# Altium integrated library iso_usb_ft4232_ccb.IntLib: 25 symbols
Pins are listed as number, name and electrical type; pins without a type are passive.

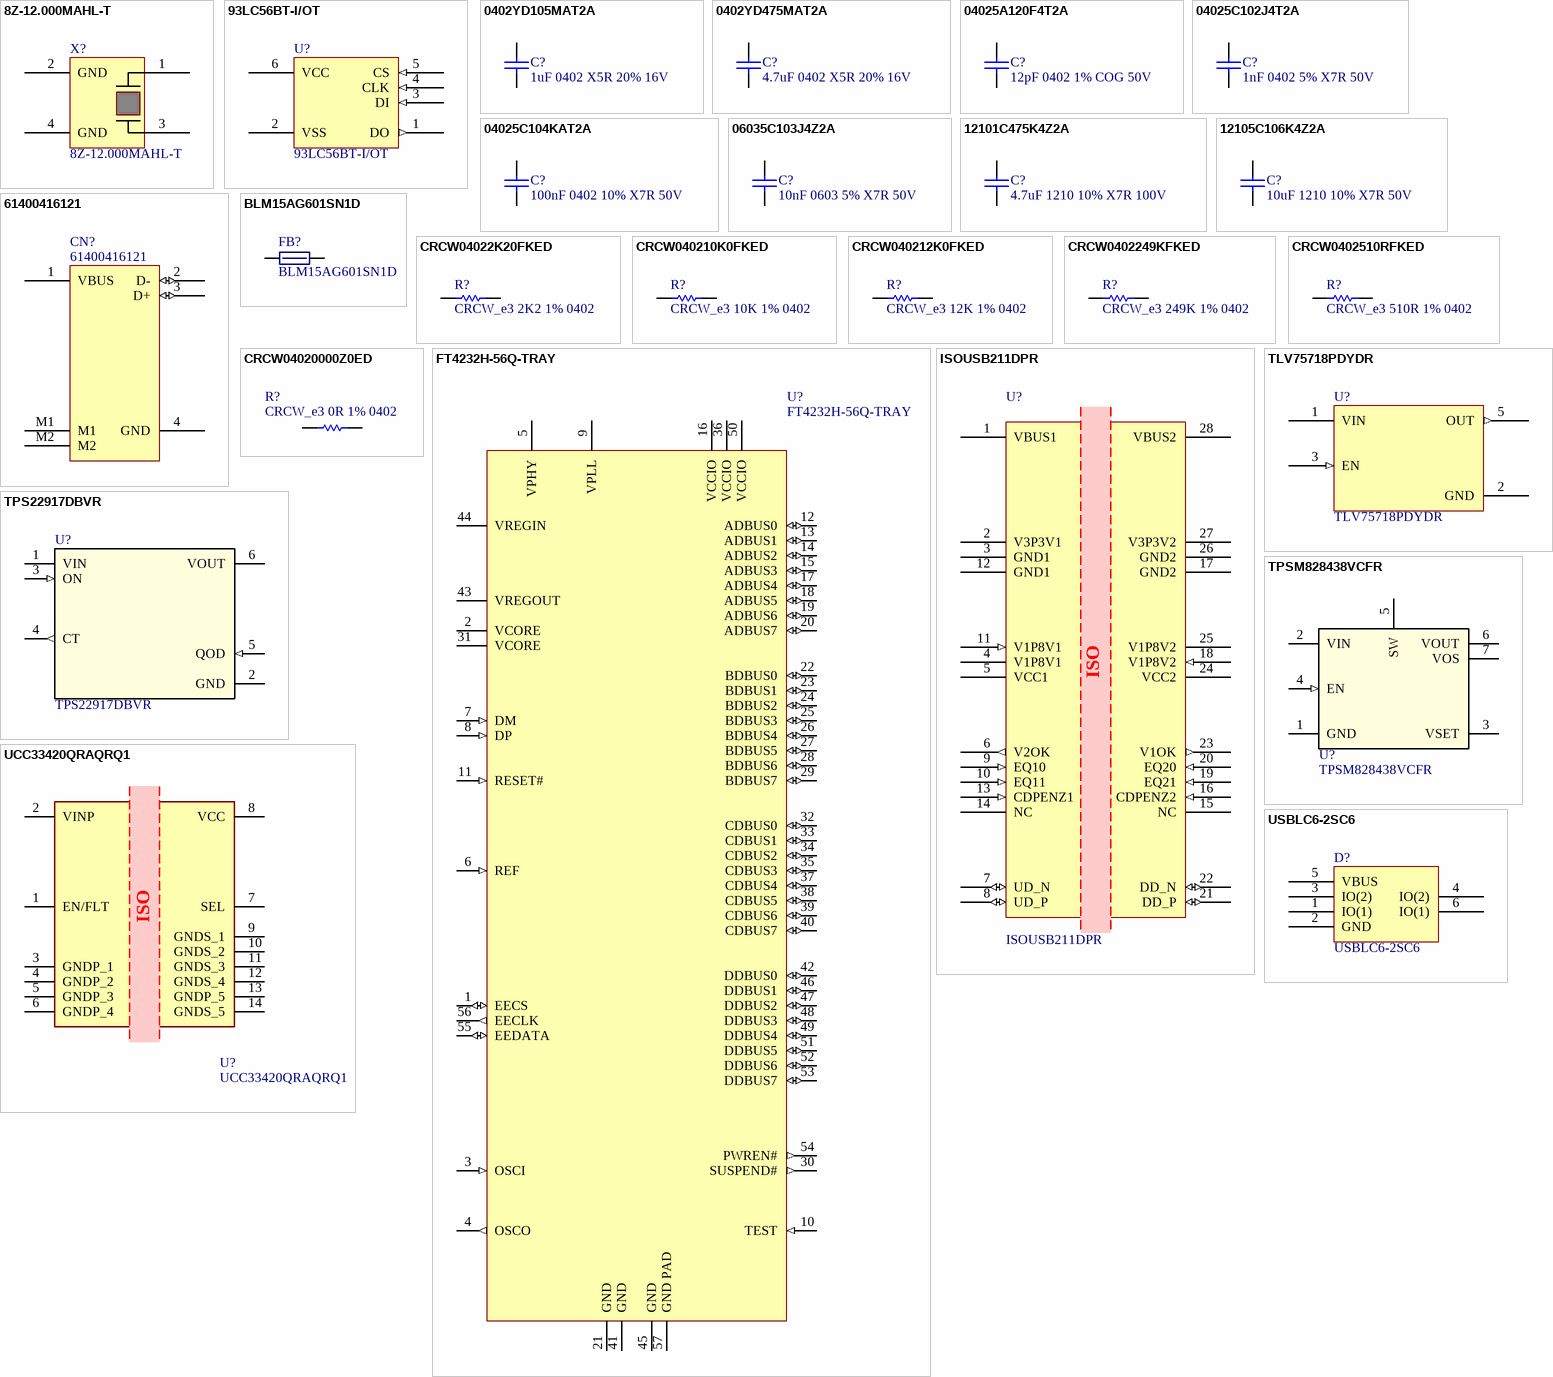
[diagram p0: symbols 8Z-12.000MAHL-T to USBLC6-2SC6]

## 8Z-12.000MAHL-T
designator X?
Crystals 12MHz 30ppm 22pF -40C +85C  2.5mm X 2mm; Manufacturer: TXC
footprint OSCCC250X200X55L65X80-TXC-8ZL (Oscillator, Corner Concave; 2.50 mm L X 2.00 mm W X 0.55 mm H body)
footprint OSCCC250X200X55L65X80-TXC-8ZN (Oscillator, Corner Concave; 2.50 mm L X 2.00 mm W X 0.55 mm H body)
pins: 1, 2 GND (power), 3, 4 GND (power)

## 93LC56BT-I/OT
designator U?
MICROCHIP - 93LC56BT-I/OT - IC, EEPROM, 2KBIT, SERIAL, 3MHZ SOT-23-6
footprint SOT23-6P95_280X145L45X37N (Small Outline Transistor (SOT23), 0.95 mm pitch; 6 pin, 2.90 mm L X 1.60 mm W X 1.45 mm H body)
pins: 1 DO (out), 2 VSS (power), 3 DI (in), 4 CLK (in), 5 CS (in), 6 VCC (power)

## 0402YD105MAT2A
designator C?, comment 1uF 0402 X5R 20% 16V
Multilayer Ceramic Capacitors MLCC - SMD/SMT 16V 1uF X5R 0402; Manufacturer: AVX; Manufacturer Part Number: 0402YD105MAT2A
footprint CAPC100X50X56L25L-AVX0402L (Capacitor, Chip; 1.00 mm L X 0.50 mm W X 0.56 mm H body)
footprint CAPC100X50X56L25N-AVX0402N (Capacitor, Chip; 1.00 mm L X 0.50 mm W X 0.56 mm H body)
pins: 1, 2

## 0402YD475MAT2A
designator C?, comment 4.7uF 0402 X5R 20% 16V
Multilayer Ceramic Capacitors MLCC - SMD/SMT 16V 4.7uF X5R 0402; Manufacturer: AVX; Manufacturer Part Number: 0402YD475MAT2A
footprint CAPC100X50X56L25L-AVX0402L (Capacitor, Chip; 1.00 mm L X 0.50 mm W X 0.56 mm H body)
footprint CAPC100X50X56L25N-AVX0402N (Capacitor, Chip; 1.00 mm L X 0.50 mm W X 0.56 mm H body)
pins: 1, 2

## 04025A120F4T2A
designator C?, comment 12pF 0402 1% COG 50V
Multilayer Ceramic Capacitors MLCC - SMD/SMT 50V 12pF C0G 0402 1% AEC-Q200; Manufacturer: AVX; Manufacturer Part Number: 04025A120F4T2A
footprint CAPC100X50X56L25L-AVX0402L (Capacitor, Chip; 1.00 mm L X 0.50 mm W X 0.56 mm H body)
footprint CAPC100X50X56L25N-AVX0402N (Capacitor, Chip; 1.00 mm L X 0.50 mm W X 0.56 mm H body)
pins: 1, 2

## 04025C102J4T2A
designator C?, comment 1nF 0402 5% X7R 50V
Multilayer Ceramic Capacitors MLCC - SMD/SMT 50V 1000pF X7R 0402 Tol 5% AEC-Q200; Manufacturer: AVX; Manufacturer Part Number: 04025C102J4T2A
footprint CAPC100X50X56L25L-AVX0402L (Capacitor, Chip; 1.00 mm L X 0.50 mm W X 0.56 mm H body)
footprint CAPC100X50X56L25N-AVX0402N (Capacitor, Chip; 1.00 mm L X 0.50 mm W X 0.56 mm H body)
pins: 1, 2

## 04025C104KAT2A
designator C?, comment 100nF 0402 10% X7R 50V
Multilayer Ceramic Capacitors MLCC - SMD/SMT 50V .1uF X7R 0402 10%TOL; Manufacturer: AVX; Manufacturer Part Number: 04025C104KAT2A
footprint CAPC100X50X56L25L-AVX0402L (Capacitor, Chip; 1.00 mm L X 0.50 mm W X 0.56 mm H body)
footprint CAPC100X50X56L25N-AVX0402N (Capacitor, Chip; 1.00 mm L X 0.50 mm W X 0.56 mm H body)
pins: 1, 2

## 06035C103J4Z2A
designator C?, comment 10nF 0603 5% X7R 50V
Multilayer Ceramic Capacitors MLCC - SMD/SMT 50V .01uF X7R 0603 5% TOL; Manufacturer: AVX; Manufacturer Part Number: 06035C103J4Z2A
footprint CAPC160X81X90L35L-AVX0603L (Capacitor, Chip; 1.60 mm L X 0.81 mm W X 0.90 mm H body)
footprint CAPC160X81X90L35N-AVX0603N (Capacitor, Chip; 1.60 mm L X 0.81 mm W X 0.90 mm H body)
pins: 1, 2

## 12101C475K4Z2A
designator C?, comment 4.7uF 1210 10% X7R 100V
Multilayer Ceramic Capacitors MLCC - SMD/SMT 100V 4.7uF X7R 1210 10% Tol AEC-Q200; Manufacturer: AVX; Manufacturer Part Number: 12101C475K4Z2A
footprint CAPC320X250X152L50L-AVX1210L (Capacitor, Chip; 3.20 mm L X 2.50 mm W X 1.52 mm H body)
footprint CAPC320X250X152L50N-AVX1210N (Capacitor, Chip; 3.20 mm L X 2.50 mm W X 1.52 mm H body)
pins: 1, 2

## 12105C106K4Z2A
designator C?, comment 10uF 1210 10% X7R 50V
Multilayer Ceramic Capacitors MLCC - SMD/SMT 50V 10uF X7R 1210 10%TOL AEC-Q200; Manufacturer: AVX; Manufacturer Part Number: 12105C106K4Z2A
footprint CAPC320X250X152L50L-AVX1210L (Capacitor, Chip; 3.20 mm L X 2.50 mm W X 1.52 mm H body)
footprint CAPC320X250X152L50N-AVX1210N (Capacitor, Chip; 3.20 mm L X 2.50 mm W X 1.52 mm H body)
pins: 1, 2

## 61400416121
designator CN?
USB Connectors WR-COM Type B 4Pin Horztl Female; Manufacturer: Wurth
footprint 61400416121 (USB 2.0 Type B Horizontal)
pins: 1 VBUS (power) "Power", 2 D- (io) "-DATA", 3 D+ (io) "+DATA", 4 GND, M1, M2

## BLM15AG601SN1D
designator FB?
MURATA  BLM15AG601SN1D  FERRITE, BEAD, 0402, 0.6OHM, 0.3A
footprint BEADC100X50X55L25-FB0402L (Ferrite Bead, Chip; 1.00 mm L X 0.50 mm W X 0.55 mm H body)
footprint BEADC100X50X55L25-FB0402N (Ferrite Bead, Chip; 1.00 mm L X 0.50 mm W X 0.55 mm H body)
pins: 1, 2

## CRCW04022K20FKED
designator R?, comment CRCW_e3 2K2 1% 0402
Thick Film Resistors - SMD 2K2 ohm 1%; Manufacturer: VISHAY; Manufacturer Part Number: CRCW04022K20FKED
footprint RESC100X50X40L25-CRCW0402L (Resistor, Chip; 1.00 mm L X 0.50 mm W X 0.40 mm H body)
footprint RESC100X50X40L25-CRCW0402N (Resistor, Chip; 1.00 mm L X 0.50 mm W X 0.40 mm H body)
pins: 1, 2

## CRCW040210K0FKED
designator R?, comment CRCW_e3 10K 1% 0402
Thick Film Resistors - SMD 10K ohm 1%; Manufacturer: VISHAY; Manufacturer Part Number: CRCW040210K0FKED
footprint RESC100X50X40L25-CRCW0402L (Resistor, Chip; 1.00 mm L X 0.50 mm W X 0.40 mm H body)
footprint RESC100X50X40L25-CRCW0402N (Resistor, Chip; 1.00 mm L X 0.50 mm W X 0.40 mm H body)
pins: 1, 2

## CRCW040212K0FKED
designator R?, comment CRCW_e3 12K 1% 0402
Thick Film Resistors - SMD 12K ohm 1%; Manufacturer: VISHAY; Manufacturer Part Number: CRCW040212K0FKED
footprint RESC100X50X40L25-CRCW0402L (Resistor, Chip; 1.00 mm L X 0.50 mm W X 0.40 mm H body)
footprint RESC100X50X40L25-CRCW0402N (Resistor, Chip; 1.00 mm L X 0.50 mm W X 0.40 mm H body)
pins: 1, 2

## CRCW0402249KFKED
designator R?, comment CRCW_e3 249K 1% 0402
Thick Film Resistors - SMD 249K ohm 1%; Manufacturer: VISHAY; Manufacturer Part Number: CRCW0402249KFKED
footprint RESC100X50X40L25-CRCW0402L (Resistor, Chip; 1.00 mm L X 0.50 mm W X 0.40 mm H body)
footprint RESC100X50X40L25-CRCW0402N (Resistor, Chip; 1.00 mm L X 0.50 mm W X 0.40 mm H body)
pins: 1, 2

## CRCW0402510RFKED
designator R?, comment CRCW_e3 510R 1% 0402
Thick Film Resistors - SMD 510R ohm 1%; Manufacturer: VISHAY; Manufacturer Part Number: CRCW0402510RFKED
footprint RESC100X50X40L25-CRCW0402L (Resistor, Chip; 1.00 mm L X 0.50 mm W X 0.40 mm H body)
footprint RESC100X50X40L25-CRCW0402N (Resistor, Chip; 1.00 mm L X 0.50 mm W X 0.40 mm H body)
pins: 1, 2

## CRCW04020000Z0ED
designator R?, comment CRCW_e3 0R 1% 0402
Thick Film Resistors - SMD 0 ohm 1%; Manufacturer: VISHAY; Manufacturer Part Number: CRCW04020000Z0ED
footprint RESC100X50X40L25-CRCW0402L (Resistor, Chip; 1.00 mm L X 0.50 mm W X 0.40 mm H body)
footprint RESC100X50X40L25-CRCW0402N (Resistor, Chip; 1.00 mm L X 0.50 mm W X 0.40 mm H body)
pins: 1, 2

## FT4232H-56Q-TRAY
designator U?
USB Interface IC Quad 480Mbs 4 UART USB 2.0 12Mbit; Manufacturer: FTDI
footprint QFN57P50_800X800X100L40X25T610N-FTDIQFN56N (Quad Flat No-Lead (QFN with Tab), 0.50 mm pitch; square, 14 pin X 14 pin, 8.00 mm L X 8.00 mm W X 1.00 mm H body)
pins: 1 EECS (io), 2 VCORE (power), 3 OSCI (in), 4 OSCO (out), 5 VPHY (power), 6 REF (in), 7 DM (in), 8 DP (in), 9 VPLL (power), 10 TEST (in), 11 RESET# (in), 12 ADBUS0 (io), 13 ADBUS1 (io), 14 ADBUS2 (io), 15 ADBUS3 (io), 16 VCCIO (power), 17 ADBUS4 (io), 18 ADBUS5 (io), 19 ADBUS6 (io), 20 ADBUS7 (io), 21 GND (power), 22 BDBUS0 (io), 23 BDBUS1 (io), 24 BDBUS2 (io), 25 BDBUS3 (io), 26 BDBUS4 (io), 27 BDBUS5 (io), 28 BDBUS6 (io), 29 BDBUS7 (io), 30 SUSPEND# (out), 31 VCORE (power), 32 CDBUS0 (io), 33 CDBUS1 (io), 34 CDBUS2 (io), 35 CDBUS3 (io), 36 VCCIO (power), 37 CDBUS4 (io), 38 CDBUS5 (io), 39 CDBUS6 (io), 40 CDBUS7 (io), 41 GND (power), 42 DDBUS0 (io), 43 VREGOUT (power), 44 VREGIN (power), 45 GND (power), 46 DDBUS1 (io), 47 DDBUS2 (io), 48 DDBUS3 (io), 49 DDBUS4 (io), 50 VCCIO (power), 51 DDBUS5 (io), 52 DDBUS6 (io), 53 DDBUS7 (io), 54 PWREN# (out), 55 EEDATA (io), 56 EECLK (out), 57 GND PAD (power)

## ISOUSB211DPR
designator U?
ISOUSB211-Q1 High/Full/Low Speed Isolated USB Repeater; Manufacturer: Texas Instruments
footprint DP0028A-TI
pins: 1 VBUS1 (power), 2 V3P3V1 (power), 3 GND1 (power), 4 V1P8V1 (power), 5 VCC1 (power), 6 V2OK (out), 7 UD_N (io), 8 UD_P (io), 9 EQ10 (in), 10 EQ11 (in), 11 V1P8V1 (in), 12 GND1 (power), 13 CDPENZ1 (in), 14 NC (power), 15 NC (power), 16 CDPENZ2 (in), 17 GND2 (power), 18 V1P8V2 (in), 19 EQ21 (in), 20 EQ20 (in), 21 DD_P (io), 22 DD_N (io), 23 V1OK (out), 24 VCC2 (power), 25 V1P8V2 (power), 26 GND2 (power), 27 V3P3V2 (power), 28 VBUS2 (power)

## TLV75718PDYDR
designator U?
LDO Voltage Regulators 1.8V and 1A low-IQ high-accuracy low-dropout; Manufacturer: Texas Instruments
footprint SOT23-5P95_280X145L45X35L-AP2127-SOT23-5L (Small Outline Transistor (SOT23), 0.95 mm pitch; 5 pin, 2.92 mm L X 1.60 mm W X 1.45 mm H body)
footprint SOT23-5P95_280X145L45X35N-AP2127-SOT23-5N (Small Outline Transistor (SOT23), 0.95 mm pitch; 5 pin, 2.92 mm L X 1.60 mm W X 1.45 mm H body)
pins: 1 VIN (power), 2 GND (power), 3 EN (in), 5 OUT (out)

## TPS22917DBVR
designator U?
Power Switch ICs - Power Distribution 5.5-V 2-A 80-mohm 10-nA leakage load A 595-TPS22917DBVT; Manufacturer: Texas Instruments; Manufacturer Part Number: LM5050Q0MKX-1/NOPB
footprint SOT23-6P95_280X100L40X37-LM5050-1 (Small Outline Transistor (SOT23), 0.95 mm pitch; 6 pin, 2.90 mm L X 1.625 mm W X 1.00 mm H body)
pins: 1 VIN (power), 2 GND (power), 3 ON (in), 4 CT (out), 5 QOD (in), 6 VOUT (power)

## TPSM828438VCFR
designator U?
Switching Voltage Regulators 275nA IQ 0.4V to 3. 6V selectable VOUT; Manufacturer: Texas Instruments
footprint VCF0007A-MFG
pins: 1 GND (power), 2 VIN (power), 3 VSET, 4 EN (in), 5 SW, 6 VOUT (power), 7 VOS

## UCC33420QRAQRQ1
designator U?
Power Management Modules Automotive, 5V/5V 1.5W 3kVrms isolated DC-DC module with integrated transformer; Manufacturer: Texas Instruments
footprint UCC33020QRAQRQ1
pins: 1 EN/FLT, 2 VINP, 3 GNDP_1, 4 GNDP_2, 5 GNDP_3, 6 GNDP_4, 7 SEL, 8 VCC, 9 GNDS_1, 10 GNDS_2, 11 GNDS_3, 12 GNDS_4, 13 GNDP_5, 14 GNDS_5

## USBLC6-2SC6
designator D?
ESD Suppressors / TVS Diodes ESD Protection Low Cap; Manufacturer: ST Microelectronics
footprint SOT23-6L
pins: 1 IO(1), 2 GND (power), 3 IO(2), 4 IO(2), 5 VBUS (power), 6 IO(1)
